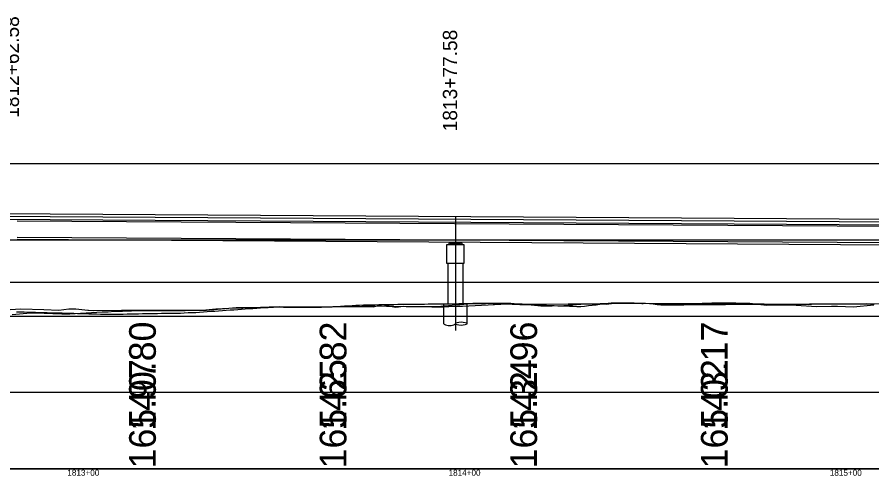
# Model space of a CAD drawing. Extents: x 2126510 to 2136144, y 865066 to 868066.
# Drawn here: x 2133885.6 to 2134109.8, y 867812.5 to 867932.8 of the extents above; entities that cross this region are included whole.
import ezdxf

# ---------------------------------------------------------------- set-up
doc = ezdxf.new("R2010")
doc.units = 0
for name, color, linetype in [('RD_DTM_BkLn1', 7, 'Continuous'), ('RD_EX_Bridge', 7, 'Continuous'), ('RD_EX_Conc_Curb', 7, 'Continuous'), ('RD_EX_GuardRail', 7, 'Continuous'), ('RD_EX_H2O', 7, 'Continuous'), ('RD_EX_Misc', 7, 'Continuous'), ('RD_EX_Misc_Golf_Cartpath', 7, 'Continuous'), ('RD_EX_UT', 7, 'Continuous'), ('RD_HC_Data', 7, 'Continuous'), ('RD_HC_txCode', 7, 'Continuous')]:
    doc.layers.add(name, color=color, linetype=linetype)

msp = doc.modelspace()

# ---------------------------------------------------------------- linework, layer by layer
at = {"layer": 'RD_DTM_BkLn1'}
for p, q in [((2133649.16, 867881.28), (2134230.74, 867877.62)), ((2134002.32, 867873.53), (2133998.82, 867873.53)), ((2133998.82, 867873.53), (2133998.82, 867873.19)), ((2133999.24, 867873.53), (2134001.9, 867873.53)), ((2134002.32, 867873.19), (2134002.32, 867873.53)), ((2133998.57, 867868.19), (2133998.57, 867857.62)), ((2134002.57, 867868.19), (2134002.57, 867857.67))]:
    msp.add_line(p, q, dxfattribs=at)
msp.add_lwpolyline([(2133998.32, 867873.19), (2134002.82, 867873.19), (2134002.82, 867868.19), (2133998.32, 867868.19)], close=True, dxfattribs=at)
msp.add_lwpolyline([(2133997.57, 867852.4), (2133997.57, 867857.64), (2134003.57, 867857.64), (2134003.57, 867852.4)], dxfattribs=at)
msp.add_ellipse((2134002.07, 867852.4), major_axis=(-1.5, 0), ratio=0.310397, dxfattribs=at)
msp.add_ellipse((2133999.07, 867852.4), major_axis=(-1.5, 0), ratio=0.310397, start_param=0, end_param=3.141593, dxfattribs=at)
at = {"layer": 'RD_EX_Bridge'}
for p, q in [((2133999.24, 867873.82), (2133999.24, 867873.53)), ((2134001.9, 867873.53), (2134001.9, 867873.82))]:
    msp.add_line(p, q, dxfattribs=at)
at = {"layer": 'RD_EX_Conc_Curb'}
msp.add_lwpolyline([(2133884.33, 867854.82), (2133889.12, 867855.2), (2133889.48, 867855.22), (2133889.66, 867855.23), (2133889.7, 867855.22), (2133890.32, 867855.21), (2133897.38, 867854.98), (2133899.43, 867855), (2133907.93, 867855.47), (2133909.54, 867855.52), (2133911.14, 867855.68), (2133913.22, 867855.72), (2133915.64, 867855.78), (2133919.75, 867855.81), (2133922.14, 867855.81), (2133927.14, 867855.82), (2133929.67, 867855.87), (2133935.31, 867855.93), (2133943.06, 867856.61), (2133943.31, 867856.62), (2133952.08, 867856.76), (2133952.86, 867856.77), (2133958.49, 867856.81), (2133962.99, 867856.82), (2133974.48, 867856.9), (2133979.01, 867856.81), (2133981.56, 867857.47), (2133984.4, 867856.79), (2133984.96, 867856.76), (2133986.97, 867857.03), (2133991.47, 867856.87), (2133995.7, 867856.93), (2134004.78, 867857.73), (2134005.17, 867857.76), (2134006.09, 867857.79), (2134007.91, 867857.79), (2134009.73, 867857.79), (2134015.08, 867857.78), (2134016.03, 867857.69), (2134018.41, 867857.52), (2134020.84, 867857.51), (2134030.2, 867857.62), (2134031.46, 867857.6), (2134034.6, 867857.63), (2134040.12, 867857.53), (2134042.23, 867857.8), (2134047.26, 867857.77), (2134047.47, 867857.76), (2134049.5, 867857.65), (2134049.87, 867857.65), (2134065.3, 867857.77), (2134065.89, 867857.81), (2134067.85, 867857.82), (2134074.15, 867857.82), (2134077.39, 867857.81), (2134077.83, 867857.8), (2134082.17, 867857.26), (2134087.82, 867857.38), (2134092.47, 867857.49), (2134093.29, 867857.47), (2134094.73, 867857.58), (2134105.07, 867857.58), (2134105.15, 867857.59), (2134109.81, 867857.64), (2134112.51, 867857.67)], dxfattribs=at)
at = {"layer": 'RD_EX_GuardRail'}
for p, q in [((2135251.98, 867894.32), (2130671.73, 867894.32)), ((2135251.98, 867874.32), (2133154.4, 867874.32)), ((2135251.98, 867854.32), (2130671.73, 867854.32)), ((2135251.98, 867834.32), (2130671.73, 867834.32)), ((2135251.98, 867814.32), (2130671.73, 867814.32))]:
    msp.add_line(p, q, dxfattribs=at)
at = {"layer": 'RD_EX_H2O'}
for points in [[(2133886.47, 867855.5), (2133887.47, 867855.47), (2133888.47, 867855.45), (2133889.47, 867855.42), (2133890.47, 867855.39), (2133891.47, 867855.36), (2133892.47, 867855.34), (2133893.47, 867855.31), (2133894.47, 867855.28), (2133895.47, 867855.26), (2133896.47, 867855.23), (2133897.47, 867855.2), (2133898.47, 867855.18), (2133899.47, 867855.15), (2133900.47, 867855.12), (2133901.47, 867855.1), (2133902.47, 867855.07), (2133903.47, 867855.04), (2133904.47, 867855.01), (2133905.47, 867854.99), (2133906.47, 867854.96), (2133907.47, 867854.93), (2133908.47, 867854.91), (2133909.47, 867854.88), (2133910.47, 867854.87), (2133911.47, 867854.88), (2133912.47, 867854.9), (2133913.47, 867854.92), (2133914.47, 867854.94), (2133915.47, 867854.96), (2133916.47, 867854.98), (2133917.47, 867855), (2133918.47, 867855.03), (2133919.47, 867855.05), (2133920.47, 867855.07), (2133921.47, 867855.09), (2133922.47, 867855.11), (2133923.47, 867855.13), (2133924.47, 867855.15), (2133925.47, 867855.17), (2133926.47, 867855.19), (2133927.47, 867855.18), (2133928.47, 867855.18), (2133929.47, 867855.22), (2133930.47, 867855.31), (2133931.47, 867855.33), (2133932.47, 867855.36), (2133933.47, 867855.43), (2133934.47, 867855.5), (2133935.47, 867855.57), (2133936.47, 867855.64), (2133937.47, 867855.71), (2133938.47, 867855.78), (2133939.47, 867855.85), (2133940.47, 867855.92), (2133941.47, 867855.99), (2133942.47, 867856.06), (2133943.47, 867856.13), (2133944.47, 867856.2), (2133945.47, 867856.27), (2133946.47, 867856.34), (2133947.47, 867856.41), (2133948.47, 867856.48), (2133949.47, 867856.55), (2133950.47, 867856.62), (2133951.47, 867856.68), (2133952.47, 867856.75), (2133953.47, 867856.82), (2133954.47, 867856.86), (2133955.47, 867856.73), (2133956.47, 867856.72), (2133957.47, 867856.73), (2133958.47, 867856.74), (2133959.47, 867856.75), (2133960.47, 867856.75), (2133961.47, 867856.76), (2133962.47, 867856.76), (2133963.47, 867856.77), (2133964.47, 867856.77), (2133965.47, 867856.77), (2133966.47, 867856.78), (2133967.47, 867856.83), (2133968.47, 867856.88), (2133969.47, 867856.94), (2133970.47, 867857), (2133971.47, 867857.05), (2133972.47, 867857.11), (2133973.47, 867857.16), (2133974.47, 867857.22), (2133975.47, 867857.27), (2133976.47, 867857.31), (2133977.47, 867857.34), (2133978.47, 867857.36), (2133979.47, 867857.38), (2133980.47, 867857.4), (2133981.47, 867857.42), (2133982.47, 867857.43), (2133983.47, 867857.45), (2133984.47, 867857.47), (2133985.47, 867857.48), (2133986.47, 867857.49)], [(2133986.47, 867857.49), (2133987.47, 867857.49), (2133988.47, 867857.51), (2133989.47, 867857.52), (2133990.47, 867857.53), (2133991.47, 867857.54), (2133992.47, 867857.55), (2133993.47, 867857.56), (2133994.47, 867857.57), (2133995.47, 867857.59), (2133996.47, 867857.6), (2133997.47, 867857.61), (2133998.47, 867857.62), (2133999.47, 867857.63), (2134000.47, 867857.64), (2134001.47, 867857.65), (2134002.47, 867857.66), (2134003.47, 867857.68), (2134004.47, 867857.69), (2134005.47, 867857.7), (2134006.47, 867857.71), (2134007.47, 867857.72), (2134008.47, 867857.73), (2134009.47, 867857.75), (2134010.47, 867857.73), (2134011.47, 867857.73), (2134012.47, 867857.66), (2134013.47, 867857.6), (2134014.47, 867857.57), (2134015.47, 867857.53), (2134016.47, 867857.5), (2134017.47, 867857.46), (2134018.47, 867857.43), (2134019.47, 867857.39), (2134020.47, 867857.36), (2134021.47, 867857.33), (2134022.47, 867857.29), (2134023.47, 867857.26), (2134024.47, 867857.22), (2134025.47, 867857.19), (2134026.47, 867857.15), (2134027.47, 867857.12), (2134028.47, 867857.08), (2134029.47, 867857.05), (2134030.47, 867857.01), (2134031.47, 867856.98), (2134032.47, 867856.94), (2134033.47, 867856.91), (2134034.47, 867857.01), (2134035.47, 867857.13), (2134036.47, 867857.25), (2134037.47, 867857.37), (2134038.47, 867857.48), (2134039.47, 867857.6), (2134040.47, 867857.71), (2134041.47, 867857.83), (2134042.47, 867857.9), (2134043.47, 867857.88), (2134044.47, 867857.87), (2134045.47, 867857.85), (2134046.47, 867857.84), (2134047.47, 867857.82), (2134048.47, 867857.81), (2134049.47, 867857.79), (2134050.47, 867857.78), (2134051.47, 867857.72), (2134052.47, 867857.56), (2134053.47, 867857.4), (2134054.47, 867857.34), (2134055.47, 867857.35), (2134056.47, 867857.35), (2134057.47, 867857.36), (2134058.47, 867857.37), (2134059.47, 867857.38), (2134060.47, 867857.38), (2134061.47, 867857.39), (2134062.47, 867857.4), (2134063.47, 867857.41), (2134064.47, 867857.42), (2134065.47, 867857.42), (2134066.47, 867857.43), (2134067.47, 867857.44), (2134068.47, 867857.45), (2134069.47, 867857.45), (2134070.47, 867857.46), (2134071.47, 867857.47), (2134072.47, 867857.49), (2134073.47, 867857.48), (2134074.47, 867857.48), (2134075.47, 867857.48), (2134076.47, 867857.48), (2134077.47, 867857.49), (2134078.47, 867857.49), (2134079.47, 867857.5), (2134080.47, 867857.5), (2134081.47, 867857.5), (2134082.47, 867857.51), (2134083.47, 867857.51), (2134084.47, 867857.52), (2134085.47, 867857.52), (2134086.47, 867857.53)], [(2134086.47, 867857.53), (2134087.47, 867857.53), (2134088.47, 867857.54), (2134089.47, 867857.54), (2134090.47, 867857.55), (2134091.47, 867857.55), (2134092.47, 867857.55), (2134093.47, 867857.56), (2134094.47, 867857.56), (2134095.47, 867857.57), (2134096.47, 867857.57), (2134097.47, 867857.58), (2134098.47, 867857.58), (2134099.47, 867857.59), (2134100.47, 867857.59), (2134101.47, 867857.6), (2134102.47, 867857.6), (2134103.47, 867857.61), (2134104.47, 867857.62), (2134105.47, 867857.63), (2134106.47, 867857.64), (2134107.47, 867857.64), (2134108.47, 867857.65), (2134109.47, 867857.61), (2134110.47, 867857.55)], [(2133885.47, 867855.53), (2133886.47, 867855.5)]]:
    msp.add_lwpolyline(points, dxfattribs=at)
at = {"layer": 'RD_EX_Misc'}
for p, q in [((2133649.16, 867882.7), (2134667.76, 867876.29)), ((2131523, 867814.32), (2135677.25, 867814.32))]:
    msp.add_line(p, q, dxfattribs=at)
msp.add_lwpolyline([(2131430.13, 867814.32), (2131430.13, 867863.32), (2136143.96, 867863.32)], dxfattribs=at)
at = {"layer": 'RD_EX_Misc_Golf_Cartpath'}
msp.add_lwpolyline([(2133879.58, 867855.83), (2133886.56, 867856.27), (2133892.61, 867856.1), (2133896.53, 867855.94), (2133899.18, 867856.33), (2133901.01, 867856.3), (2133901.84, 867856.23), (2133904.13, 867855.96), (2133904.32, 867855.9), (2133905.55, 867855.88), (2133912.99, 867855.92), (2133914.94, 867855.92), (2133922.25, 867855.94), (2133923.71, 867855.94), (2133926.91, 867855.94), (2133928.5, 867855.95), (2133934.26, 867855.96), (2133937.78, 867856.33), (2133941.18, 867856.46), (2133944.84, 867856.53), (2133951.73, 867856.8), (2133953.06, 867856.82), (2133953.37, 867856.82), (2133958.87, 867856.82), (2133959.9, 867856.8), (2133960.1, 867856.84), (2133961.59, 867856.82), (2133968.23, 867856.82), (2133970.07, 867856.88), (2133973.2, 867856.89), (2133978.72, 867857.04), (2133979.24, 867857.04), (2133982.49, 867857.01), (2133984.38, 867856.99), (2133987.63, 867856.9), (2133990.3, 867856.91), (2133994.4, 867856.82), (2133997.33, 867856.81), (2133998.88, 867856.86), (2134000.96, 867856.95), (2134002.41, 867857.02), (2134014.16, 867857.61), (2134018.13, 867857.59), (2134022.95, 867857.05), (2134023.04, 867857.05), (2134025.99, 867857.07), (2134029.06, 867857.13), (2134034.6, 867857.56), (2134038.58, 867857.67), (2134042.72, 867857.85), (2134044.24, 867857.81), (2134046.78, 867857.8), (2134048.02, 867857.8), (2134051.81, 867857.71), (2134061.44, 867857.65), (2134062.03, 867857.67), (2134067, 867857.6), (2134067.18, 867857.59), (2134067.61, 867857.58), (2134072.54, 867857.59), (2134080.61, 867857.64), (2134081.57, 867857.64), (2134089.99, 867857.21), (2134095.27, 867856.86), (2134099.21, 867857.01), (2134100.84, 867857.02), (2134105.04, 867856.85), (2134110.33, 867857.37)], dxfattribs=at)
at = {"layer": 'RD_EX_UT'}
msp.add_line((2133649.16, 867882.01), (2134667.76, 867875.59), dxfattribs=at)
at = {"layer": 'RD_HC_Data'}
msp.add_line((2134000.57, 867880.49), (2134000.57, 867850.59), dxfattribs=at)
at = {"layer": 'RD_HC_txCode'}
for p, q in [((2133885.65, 867879.37), (2134227.4, 867877.22)), ((2133885.65, 867875.12), (2134227.4, 867872.97)), ((2133885.65, 867874.54), (2134227.4, 867872.39))]:
    msp.add_line(p, q, dxfattribs=at)

# ---------------------------------------------------------------- texts
at = {"layer": 'RD_EX_Misc'}
for s, height, p in [('1812+62.58', 3.75, (2133886.11, 867906.36)), ('1813+77.58', 3.75, (2134001.04, 867902.83)), ('140.80', 7, (2133922, 867824.32)), ('142.82', 7, (2133972, 867824.32)), ('142.96', 7, (2134022, 867824.32)), ('143.17', 7, (2134072, 867824.32)), ('165.97', 7, (2133922, 867814.47)), ('165.65', 7, (2133972, 867814.47)), ('165.34', 7, (2134022, 867814.47)), ('165.02', 7, (2134072, 867814.47))]:
    msp.add_text(s, height=height, rotation=90, dxfattribs=at).set_placement(p)
for s, p in [('1813+00', (2133898.79, 867812.52)), ('1814+00', (2133998.79, 867812.52)), ('1815+00', (2134098.79, 867812.52))]:
    msp.add_text(s, height=1.6, dxfattribs=at).set_placement(p)

doc.saveas('drawing.dxf')
